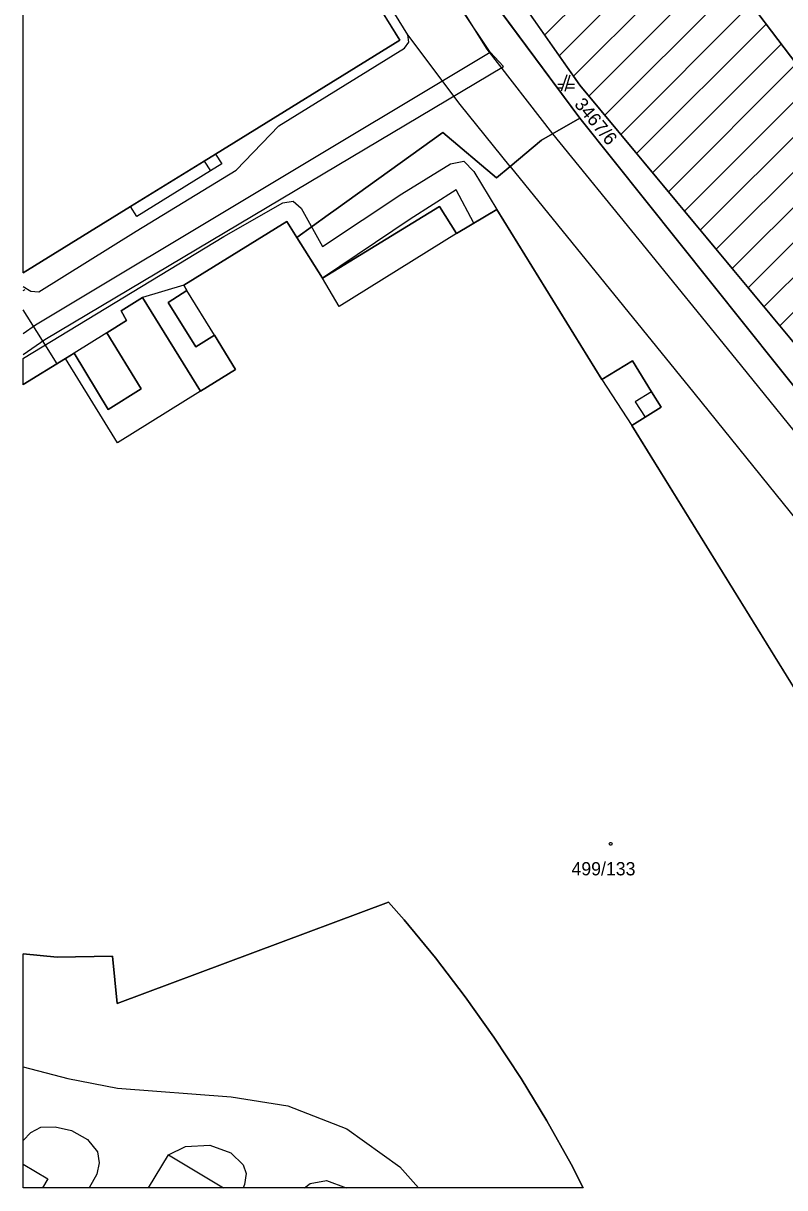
# Model space of a CAD drawing. Extents: x -264309 to -263505, y -1242443 to -1241763.
# Drawn here: x -264307.7 to -264215.7, y -1242443.4 to -1242302.6 of the extents above; entities that cross this region are included whole.
import ezdxf

# ---------------------------------------------------------------- set-up
doc = ezdxf.new("R2010")
doc.units = 0
for name, color, linetype in [('KN_2019_08_16', 7, 'Continuous'), ('KN_2019_08_16_KLADPAR', 7, 'Continuous'), ('KN_2019_08_16_ZAPPAR', 7, 'Continuous'), ('SRAFY_PARCELY', 7, 'Continuous')]:
    doc.layers.add(name, color=color, linetype=linetype)

msp = doc.modelspace()

# ---------------------------------------------------------------- linework, layer by layer
at = {"layer": 'KN_2019_08_16'}
for p, q in [((-264256.1, -1242319.6), (-264254.45, -1242319.29)), ((-264254.45, -1242319.29), (-264253.25, -1242320.54)), ((-264261.98, -1242323.23), (-264256.1, -1242319.6)), ((-264253.25, -1242320.54), (-264250.47, -1242325.12)), ((-264271.54, -1242329.59), (-264261.98, -1242323.23)), ((-264255.38, -1242322.76), (-264260.94, -1242326.3)), ((-264253.24, -1242326.77), (-264255.38, -1242322.76)), ((-264283.5, -1242328.4), (-264276.36, -1242324.32)), ((-264276.36, -1242324.32), (-264275.12, -1242324.12)), ((-264275.12, -1242324.12), (-264274.12, -1242324.99)), ((-264274.12, -1242324.99), (-264271.54, -1242329.59)), ((-264250.47, -1242325.12), (-264253.24, -1242326.77)), ((-264275.88, -1242326.58), (-264288.33, -1242334.3)), ((-264274.66, -1242328.5), (-264275.88, -1242326.58)), ((-264260.94, -1242326.3), (-264271.55, -1242333.42)), ((-264307.72, -1242343.13), (-264283.5, -1242328.4)), ((-264271.55, -1242333.42), (-264274.66, -1242328.5)), ((-264288.33, -1242334.3), (-264293.34, -1242335.76)), ((-264293.34, -1242335.76), (-264295.92, -1242337.4)), ((-264295.92, -1242337.4), (-264295.26, -1242338.55)), ((-264295.26, -1242338.55), (-264297.65, -1242340.06)), ((-264297.65, -1242340.06), (-264301.61, -1242342.52)), ((-264307.74, -1242343.14), (-264307.72, -1242343.13)), ((-264307.74, -1242346.32), (-264307.74, -1242343.14)), ((-264302.63, -1242343.16), (-264307.74, -1242346.32)), ((-264301.61, -1242342.52), (-264302.63, -1242343.16))]:
    msp.add_line(p, q, dxfattribs=at)
for points in [[(-264307.74, -1242340.12), (-264306.25, -1242339.09), (-264251.27, -1242306.11), (-264275.75, -1242269.48), (-264281.42, -1242252.63), (-264280.19, -1242222.16), (-264293.61, -1242200.69), (-264307.74, -1242192.28)], [(-264307.74, -1242342.66), (-264305.12, -1242340.86), (-264249.68, -1242307.84), (-264251.27, -1242306.11)], [(-264307.74, -1242334.91), (-264307.5, -1242334.8)], [(-264303.64, -1242343.78), (-264304.92, -1242341.75), (-264307.74, -1242337.27)]]:
    msp.add_lwpolyline(points, dxfattribs=at)
at = {"layer": 'KN_2019_08_16_KLADPAR'}
for p, q in [((-264307.74, -1242332.8), (-264307.74, -1242239.64)), ((-264287.91, -1242263.04), (-264262.22, -1242304.65)), ((-264272.98, -1242263.62), (-264240.46, -1242310.08)), ((-264240.44, -1242314.08), (-264274.26, -1242268.44)), ((-264262.22, -1242304.65), (-264284.51, -1242318.43)), ((-264242, -1242308.83), (-264242.7, -1242310.83)), ((-264242.2, -1242310.83), (-264241.6, -1242308.83)), ((-264242.42, -1242310.03), (-264243.1, -1242310.03)), ((-264243.1, -1242310.43), (-264242.56, -1242310.43)), ((-264242.08, -1242310.43), (-264241.1, -1242310.43)), ((-264241.1, -1242310.03), (-264241.96, -1242310.03)), ((-264240.46, -1242310.08), (-264207.32, -1242349.97)), ((-264243.73, -1242315.98), (-264240.44, -1242314.08)), ((-264194.62, -1242371.54), (-264240.44, -1242314.08)), ((-264240.44, -1242314.08), (-264194.62, -1242371.54)), ((-264269.9, -1242325.08), (-264257.02, -1242315.82)), ((-264257.02, -1242315.82), (-264250.5, -1242321.3)), ((-264248.85, -1242319.92), (-264245.06, -1242316.74)), ((-264245.06, -1242316.74), (-264243.73, -1242315.98)), ((-264285.87, -1242319.27), (-264294.78, -1242324.78)), ((-264284.51, -1242318.43), (-264285.87, -1242319.27)), ((-264250.5, -1242321.3), (-264248.85, -1242319.92)), ((-264294.78, -1242324.78), (-264307.74, -1242332.8)), ((-264257.43, -1242324.76), (-264271.55, -1242333.42)), ((-264270.86, -1242325.76), (-264269.9, -1242325.08)), ((-264255.37, -1242328.04), (-264257.43, -1242324.76)), ((-264250.47, -1242325.12), (-264255.37, -1242328.04)), ((-264237.76, -1242345.69), (-264250.47, -1242325.12)), ((-264274.66, -1242328.5), (-264270.86, -1242325.76)), ((-264271.55, -1242333.42), (-264274.66, -1242328.5)), ((-264234.07, -1242343.42), (-264237.76, -1242345.69)), ((-264231.76, -1242347.17), (-264234.07, -1242343.42)), ((-264230.6, -1242349.05), (-264231.76, -1242347.17)), ((-264232.55, -1242350.25), (-264230.6, -1242349.05)), ((-264234.16, -1242351.24), (-264232.55, -1242350.25)), ((-264202.64, -1242402.25), (-264234.16, -1242351.24)), ((-264296.4, -1242421.16), (-264263.59, -1242408.9)), ((-264263.59, -1242408.9), (-264261.7, -1242411.03)), ((-264261.7, -1242411.03), (-264257.89, -1242415.64)), ((-264307.74, -1242443.45), (-264307.74, -1242415.15)), ((-264307.74, -1242415.15), (-264303.63, -1242415.56)), ((-264303.63, -1242415.56), (-264296.94, -1242415.46)), ((-264296.94, -1242415.46), (-264296.4, -1242421.16)), ((-264257.89, -1242415.64), (-264254.31, -1242420.35)), ((-264254.31, -1242420.35), (-264250.83, -1242425.26)), ((-264250.83, -1242425.26), (-264247.55, -1242430.25)), ((-264247.55, -1242430.25), (-264244.42, -1242435.37)), ((-264244.42, -1242435.37), (-264241.49, -1242440.6)), ((-264241.49, -1242440.6), (-264240.03, -1242443.45)), ((-264240.03, -1242443.45), (-264307.74, -1242443.45))]:
    msp.add_line(p, q, dxfattribs=at)
for points in [[(-264187.74, -1242315.7), (-264201.06, -1242324.01), (-264208.73, -1242314.82), (-264233.72, -1242281.89), (-264276.4, -1242228.3), (-264264.01, -1242217.15), (-264213.92, -1242283.84)], [(-264236.63, -1242401.7), (-264236.54, -1242401.85), (-264236.63, -1242402), (-264236.81, -1242402), (-264236.9, -1242401.85), (-264236.81, -1242401.7)]]:
    msp.add_lwpolyline(points, close=True, dxfattribs=at)
for points in [[(-264307.74, -1242332.8), (-264294.78, -1242324.78), (-264285.87, -1242319.27), (-264284.51, -1242318.43), (-264262.22, -1242304.65), (-264287.91, -1242263.04)], [(-264155.07, -1242401.25), (-264191.23, -1242369.48), (-264207.32, -1242349.97), (-264240.46, -1242310.08), (-264272.98, -1242263.62)], [(-264274.26, -1242268.44), (-264240.44, -1242314.08), (-264243.73, -1242315.98), (-264245.06, -1242316.74), (-264248.85, -1242319.92), (-264250.5, -1242321.3), (-264257.02, -1242315.82), (-264269.9, -1242325.08), (-264270.86, -1242325.76), (-264274.66, -1242328.5), (-264275.88, -1242326.58), (-264288.33, -1242334.3), (-264287.98, -1242334.94), (-264290.24, -1242336.39), (-264286.88, -1242341.74), (-264284.62, -1242340.32), (-264282.07, -1242344.5), (-264286.31, -1242347.1), (-264293.34, -1242335.76), (-264295.92, -1242337.4), (-264295.26, -1242338.55), (-264297.65, -1242340.06), (-264293.49, -1242346.84), (-264297.49, -1242349.33), (-264301.61, -1242342.52), (-264302.63, -1242343.16), (-264307.74, -1242346.31)], [(-264233.72, -1242281.89), (-264208.73, -1242314.82), (-264201.06, -1242324.01), (-264176.92, -1242352.91), (-264157.91, -1242376.09), (-264146.94, -1242365.35), (-264103.64, -1242332.03), (-264115.27, -1242315.84), (-264099.36, -1242306.05), (-264045.86, -1242306.31)], [(-264307.74, -1242346.31), (-264302.63, -1242343.16), (-264301.61, -1242342.52), (-264297.49, -1242349.33), (-264293.49, -1242346.84), (-264297.65, -1242340.06), (-264295.26, -1242338.55), (-264295.92, -1242337.4), (-264293.34, -1242335.76), (-264286.31, -1242347.1), (-264282.07, -1242344.5), (-264284.62, -1242340.32), (-264286.88, -1242341.74), (-264290.24, -1242336.39), (-264287.98, -1242334.94), (-264288.33, -1242334.3), (-264275.88, -1242326.58), (-264274.66, -1242328.5), (-264271.55, -1242333.42), (-264257.43, -1242324.76), (-264255.37, -1242328.04), (-264250.47, -1242325.12), (-264237.76, -1242345.69), (-264234.07, -1242343.42), (-264231.76, -1242347.17), (-264230.6, -1242349.05), (-264232.55, -1242350.25), (-264234.16, -1242351.24), (-264202.64, -1242402.25)], [(-264240.03, -1242443.45), (-264241.49, -1242440.6), (-264244.42, -1242435.37), (-264247.55, -1242430.25), (-264250.83, -1242425.26), (-264254.31, -1242420.35), (-264257.89, -1242415.64), (-264261.7, -1242411.03), (-264263.59, -1242408.9), (-264296.4, -1242421.16), (-264296.94, -1242415.46), (-264303.63, -1242415.56)], [(-264303.63, -1242415.56), (-264307.74, -1242415.15)]]:
    msp.add_lwpolyline(points, dxfattribs=at)
at = {"layer": 'KN_2019_08_16_ZAPPAR'}
for p, q in [((-264276.56, -1242265.77), (-264251.67, -1242305.76)), ((-264254.92, -1242312.43), (-264261.26, -1242304)), ((-264251.67, -1242305.76), (-264243.73, -1242315.98)), ((-264248.85, -1242319.92), (-264254.92, -1242312.43)), ((-264285.87, -1242319.27), (-264285.1, -1242320.45)), ((-264284.51, -1242318.43), (-264283.75, -1242319.61)), ((-264285.1, -1242320.45), (-264294.01, -1242325.96)), ((-264283.75, -1242319.61), (-264285.1, -1242320.45)), ((-264294.01, -1242325.96), (-264294.78, -1242324.78)), ((-264305.88, -1242335.11), (-264294.08, -1242327.76)), ((-264255.37, -1242328.04), (-264269.53, -1242336.87)), ((-264269.53, -1242336.87), (-264271.55, -1242333.42)), ((-264284.62, -1242340.32), (-264287.98, -1242334.94)), ((-264296.36, -1242353.34), (-264302.63, -1242343.16)), ((-264237.76, -1242345.69), (-264234.16, -1242351.24)), ((-264286.31, -1242347.1), (-264296.36, -1242353.34)), ((-264231.76, -1242347.17), (-264233.74, -1242348.4)), ((-264233.74, -1242348.4), (-264232.55, -1242350.25)), ((-264307.74, -1242428.82), (-264302.34, -1242430.25)), ((-264301.92, -1242436.52), (-264299.98, -1242437.61)), ((-264285.18, -1242438.29), (-264282.64, -1242439.25)), ((-264292.59, -1242443.45), (-264290.2, -1242439.46)), ((-264290.2, -1242439.46), (-264283.55, -1242443.45)), ((-264271.08, -1242442.59), (-264268.71, -1242443.45))]:
    msp.add_line(p, q, dxfattribs=at)
for points in [[(-264294.08, -1242327.76), (-264281.99, -1242320.38), (-264276.84, -1242315.01), (-264261.64, -1242305.63), (-264261.11, -1242304.9), (-264261.26, -1242304), (-264286.65, -1242262.93), (-264286.99, -1242263.13), (-264287.49, -1242261.77), (-264286.83, -1242235.8), (-264287.1, -1242231.47), (-264287.89, -1242227.2), (-264289.22, -1242223), (-264291.44, -1242218.02)], [(-264243.73, -1242315.98), (-264233.3, -1242328.8), (-264221.58, -1242343.23), (-264211.15, -1242356.14), (-264200.23, -1242369.71), (-264195.36, -1242375.35)], [(-264248.85, -1242319.92), (-264237.43, -1242334.06), (-264226.65, -1242347.31), (-264215.86, -1242360.68), (-264205.35, -1242373.72), (-264199.94, -1242380)], [(-264307.74, -1242334.45), (-264306.84, -1242335), (-264305.88, -1242335.11)], [(-264302.34, -1242430.25), (-264296.36, -1242431.42), (-264282.61, -1242432.47), (-264275.74, -1242433.55), (-264268.6, -1242436.34), (-264262.2, -1242440.92), (-264259.97, -1242443.45)], [(-264307.74, -1242437.73), (-264306.85, -1242436.76), (-264305.61, -1242436.12), (-264303.88, -1242436.09), (-264301.92, -1242436.52)], [(-264299.98, -1242437.61), (-264298.77, -1242439.09), (-264298.55, -1242440.43), (-264298.84, -1242441.81), (-264299.79, -1242443.45)], [(-264290.2, -1242439.46), (-264288.14, -1242438.45), (-264285.18, -1242438.29)], [(-264282.64, -1242439.25), (-264281.17, -1242440.69), (-264280.78, -1242441.72), (-264280.99, -1242443.08), (-264281.17, -1242443.45)], [(-264307.74, -1242440.61), (-264304.79, -1242442.38), (-264305.43, -1242443.45)], [(-264273.74, -1242443.45), (-264273.05, -1242442.94), (-264271.08, -1242442.59)]]:
    msp.add_lwpolyline(points, dxfattribs=at)
at = {"layer": 'SRAFY_PARCELY'}
for p, q in [((-264244.7, -1242304.03), (-264228.9, -1242288.24)), ((-264242.95, -1242306.53), (-264227.07, -1242290.65)), ((-264241.2, -1242309.02), (-264225.24, -1242293.06)), ((-264239.35, -1242311.41), (-264223.41, -1242295.47)), ((-264237.43, -1242313.73), (-264221.58, -1242297.89)), ((-264235.5, -1242316.05), (-264219.75, -1242300.3)), ((-264233.58, -1242318.37), (-264217.92, -1242302.71)), ((-264231.65, -1242320.68), (-264216.09, -1242305.12)), ((-264229.73, -1242323), (-264214.26, -1242307.53)), ((-264227.8, -1242325.32), (-264212.43, -1242309.95)), ((-264225.88, -1242327.64), (-264210.6, -1242312.36)), ((-264223.95, -1242329.95), (-264208.77, -1242314.77)), ((-264222.02, -1242332.27), (-264206.84, -1242317.09)), ((-264220.1, -1242334.59), (-264204.91, -1242319.4)), ((-264218.17, -1242336.91), (-264202.98, -1242321.71)), ((-264216.25, -1242339.22), (-264201.05, -1242324.02))]:
    msp.add_line(p, q, dxfattribs=at)

# ---------------------------------------------------------------- texts
at = {"layer": 'KN_2019_08_16_KLADPAR'}
msp.add_text('3467/6', height=1.6, rotation=309.5118, dxfattribs=at).set_placement((-264241.19, -1242312.45))
msp.add_text('499/133', height=1.6, dxfattribs=at).set_placement((-264241.45, -1242405.67))

doc.saveas('drawing.dxf')
